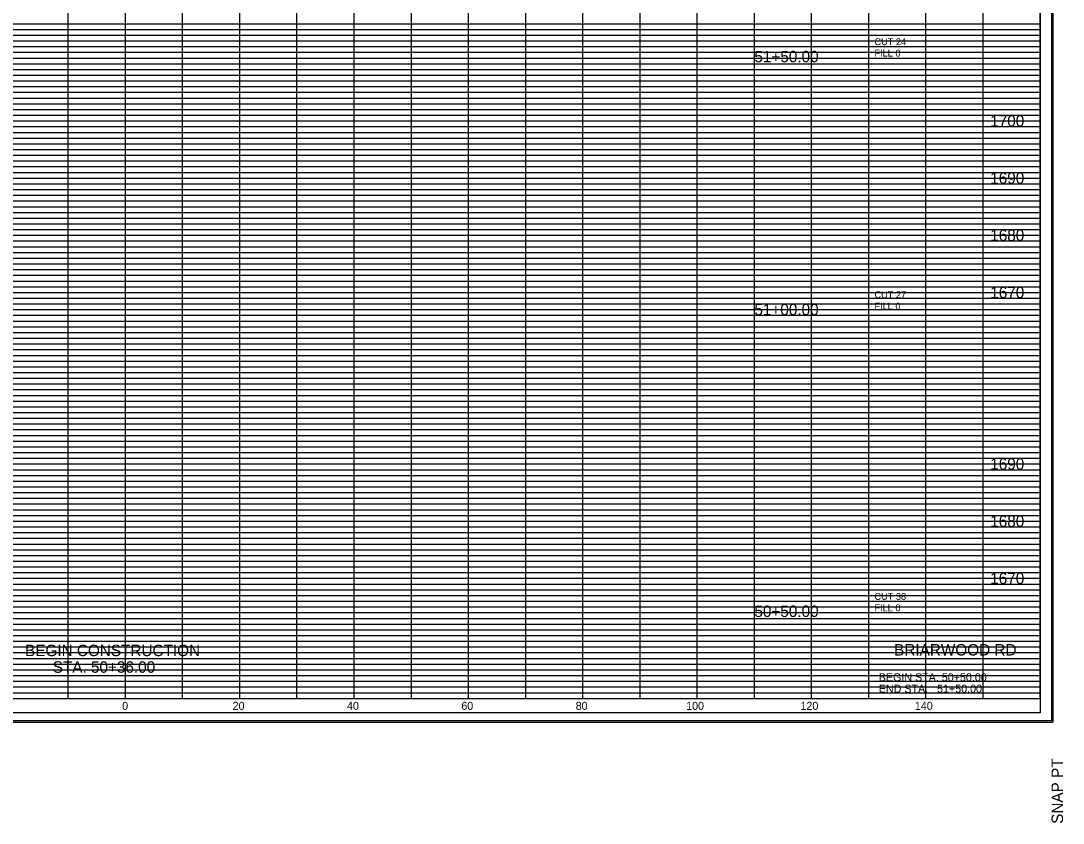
# Model space of a CAD drawing. Extents: x 980 to 2228, y 978 to 2394.
# Drawn here: x 1141.7 to 1324, y 978.2 to 1118.5 of the extents above; entities that cross this region are included whole.
import ezdxf

# ---------------------------------------------------------------- set-up
doc = ezdxf.new("R2010")
doc.units = 0
for name, color, linetype in [('DESIGN - SHEET - Corner Text', 7, 'Continuous'), ('DESIGN - SHEET - Light Grid', 7, 'Continuous'), ('DESIGN - SHEET - Linework', 7, 'Continuous'), ('DESIGN - SHEET - Plot Shape', 7, 'Continuous'), ('DESIGN - TYPICAL - Finished Grade and Subgrade', 7, 'Continuous'), ('DESIGN - TYPICAL - Text', 7, 'Continuous')]:
    doc.layers.add(name, color=color, linetype=linetype)

# ---------------------------------------------------------------- blocks, each defined once
blk = doc.blocks.new('XSTSHT')
at = {"layer": 'DESIGN - SHEET - Light Grid'}
for p, q in [((8, 11.8), (16, 11.8)), ((8, 11.7), (16, 11.7)), ((16, 11.8), (24, 11.8)), ((16, 11.7), (24, 11.7)), ((24, 11.8), (32, 11.8)), ((24, 11.7), (32, 11.7)), ((8, 11.6), (16, 11.6)), ((8, 11.5), (16, 11.5)), ((16, 11.6), (24, 11.6)), ((16, 11.5), (24, 11.5)), ((24, 11.6), (32, 11.6)), ((24, 11.5), (32, 11.5)), ((8, 11.4), (16, 11.4)), ((16, 11.4), (24, 11.4)), ((24, 11.4), (32, 11.4)), ((8, 11.3), (16, 11.3)), ((8, 11.2), (16, 11.2)), ((16, 11.3), (24, 11.3)), ((16, 11.2), (24, 11.2)), ((24, 11.3), (32, 11.3)), ((24, 11.2), (32, 11.2)), ((8, 11.1), (16, 11.1)), ((16, 11.1), (24, 11.1)), ((24, 11.1), (32, 11.1)), ((8, 10.9), (16, 10.9)), ((8, 10.8), (16, 10.8)), ((16, 10.9), (24, 10.9)), ((16, 10.8), (24, 10.8)), ((24, 10.9), (32, 10.9)), ((24, 10.8), (32, 10.8)), ((8, 10.7), (16, 10.7)), ((8, 10.6), (16, 10.6)), ((16, 10.7), (24, 10.7)), ((16, 10.6), (24, 10.6)), ((24, 10.7), (32, 10.7)), ((24, 10.6), (32, 10.6)), ((8, 10.5), (16, 10.5)), ((8, 10.4), (16, 10.4)), ((16, 10.5), (24, 10.5)), ((16, 10.4), (24, 10.4)), ((24, 10.5), (32, 10.5)), ((24, 10.4), (32, 10.4)), ((8, 10.3), (16, 10.3)), ((16, 10.3), (24, 10.3)), ((24, 10.3), (32, 10.3)), ((8, 10.2), (16, 10.2)), ((8, 10.1), (16, 10.1)), ((16, 10.2), (24, 10.2)), ((16, 10.1), (24, 10.1)), ((24, 10.2), (32, 10.2)), ((24, 10.1), (32, 10.1)), ((8, 9.9), (16, 9.9)), ((16, 9.9), (24, 9.9)), ((24, 9.9), (32, 9.9)), ((8, 9.8), (16, 9.8)), ((8, 9.7), (16, 9.7)), ((16, 9.8), (24, 9.8)), ((16, 9.7), (24, 9.7)), ((24, 9.8), (32, 9.8)), ((24, 9.7), (32, 9.7)), ((8, 9.6), (16, 9.6)), ((8, 9.5), (16, 9.5)), ((16, 9.6), (24, 9.6)), ((16, 9.5), (24, 9.5)), ((24, 9.6), (32, 9.6)), ((24, 9.5), (32, 9.5)), ((8, 9.4), (16, 9.4)), ((8, 9.3), (16, 9.3)), ((16, 9.4), (24, 9.4)), ((16, 9.3), (24, 9.3)), ((24, 9.4), (32, 9.4)), ((24, 9.3), (32, 9.3)), ((8, 9.2), (16, 9.2)), ((16, 9.2), (24, 9.2)), ((24, 9.2), (32, 9.2)), ((8, 9.1), (16, 9.1)), ((16, 9.1), (24, 9.1)), ((24, 9.1), (32, 9.1)), ((8, 8.9), (16, 8.9)), ((8, 8.8), (16, 8.8)), ((16, 8.9), (24, 8.9)), ((16, 8.8), (24, 8.8)), ((24, 8.9), (32, 8.9)), ((24, 8.8), (32, 8.8)), ((8, 8.7), (16, 8.7)), ((8, 8.6), (16, 8.6)), ((16, 8.7), (24, 8.7)), ((16, 8.6), (24, 8.6)), ((24, 8.7), (32, 8.7)), ((24, 8.6), (32, 8.6)), ((8, 8.5), (16, 8.5)), ((8, 8.4), (16, 8.4)), ((16, 8.5), (24, 8.5)), ((16, 8.4), (24, 8.4)), ((24, 8.5), (32, 8.5)), ((24, 8.4), (32, 8.4)), ((8, 8.3), (16, 8.3)), ((16, 8.3), (24, 8.3)), ((24, 8.3), (32, 8.3)), ((8, 8.2), (16, 8.2)), ((8, 8.1), (16, 8.1)), ((16, 8.2), (24, 8.2)), ((16, 8.1), (24, 8.1)), ((24, 8.2), (32, 8.2)), ((24, 8.1), (32, 8.1)), ((8, 7.9), (16, 7.9)), ((16, 7.9), (24, 7.9)), ((24, 7.9), (32, 7.9)), ((8, 7.8), (16, 7.8)), ((8, 7.7), (16, 7.7)), ((16, 7.8), (24, 7.8)), ((16, 7.7), (24, 7.7)), ((24, 7.8), (32, 7.8)), ((24, 7.7), (32, 7.7)), ((8, 7.6), (16, 7.6)), ((8, 7.5), (16, 7.5)), ((16, 7.6), (24, 7.6)), ((16, 7.5), (24, 7.5)), ((24, 7.6), (32, 7.6)), ((24, 7.5), (32, 7.5)), ((8, 7.4), (16, 7.4)), ((8, 7.3), (16, 7.3)), ((16, 7.4), (24, 7.4)), ((16, 7.3), (24, 7.3)), ((24, 7.4), (32, 7.4)), ((24, 7.3), (32, 7.3)), ((8, 7.2), (16, 7.2)), ((16, 7.2), (24, 7.2)), ((24, 7.2), (32, 7.2)), ((8, 7.1), (16, 7.1)), ((16, 7.1), (24, 7.1)), ((24, 7.1), (32, 7.1)), ((8, 6.9), (16, 6.9)), ((8, 6.8), (16, 6.8)), ((16, 6.9), (24, 6.9)), ((16, 6.8), (24, 6.8)), ((24, 6.9), (32, 6.9)), ((24, 6.8), (32, 6.8)), ((8, 6.7), (16, 6.7)), ((8, 6.6), (16, 6.6)), ((16, 6.7), (24, 6.7)), ((16, 6.6), (24, 6.6)), ((24, 6.7), (32, 6.7)), ((24, 6.6), (32, 6.6)), ((8, 6.5), (16, 6.5)), ((8, 6.4), (16, 6.4)), ((16, 6.5), (24, 6.5)), ((16, 6.4), (24, 6.4)), ((24, 6.5), (32, 6.5)), ((24, 6.4), (32, 6.4)), ((8, 6.3), (16, 6.3)), ((8, 6.2), (16, 6.2)), ((16, 6.3), (24, 6.3)), ((16, 6.2), (24, 6.2)), ((24, 6.3), (32, 6.3)), ((24, 6.2), (32, 6.2)), ((8, 6.1), (16, 6.1)), ((16, 6.1), (24, 6.1)), ((24, 6.1), (32, 6.1)), ((8, 5.9), (16, 5.9)), ((16, 5.9), (24, 5.9)), ((24, 5.9), (32, 5.9)), ((8, 5.8), (16, 5.8)), ((8, 5.7), (16, 5.7)), ((16, 5.8), (24, 5.8)), ((16, 5.7), (24, 5.7)), ((24, 5.8), (32, 5.8)), ((24, 5.7), (32, 5.7)), ((8, 5.6), (16, 5.6)), ((8, 5.5), (16, 5.5)), ((16, 5.6), (24, 5.6)), ((16, 5.5), (24, 5.5)), ((24, 5.6), (32, 5.6)), ((24, 5.5), (32, 5.5)), ((8, 5.4), (16, 5.4)), ((8, 5.3), (16, 5.3)), ((16, 5.4), (24, 5.4)), ((16, 5.3), (24, 5.3)), ((24, 5.4), (32, 5.4)), ((24, 5.3), (32, 5.3)), ((8, 5.2), (16, 5.2)), ((16, 5.2), (24, 5.2)), ((24, 5.2), (32, 5.2)), ((8, 5.1), (16, 5.1)), ((16, 5.1), (24, 5.1)), ((24, 5.1), (32, 5.1)), ((8, 4.9), (16, 4.9)), ((8, 4.8), (16, 4.8)), ((16, 4.9), (24, 4.9)), ((16, 4.8), (24, 4.8)), ((24, 4.9), (32, 4.9)), ((24, 4.8), (32, 4.8)), ((8, 4.7), (16, 4.7)), ((8, 4.6), (16, 4.6)), ((16, 4.7), (24, 4.7)), ((16, 4.6), (24, 4.6)), ((24, 4.7), (32, 4.7)), ((24, 4.6), (32, 4.6)), ((8, 4.5), (16, 4.5)), ((8, 4.4), (16, 4.4)), ((16, 4.5), (24, 4.5)), ((16, 4.4), (24, 4.4)), ((24, 4.5), (32, 4.5)), ((24, 4.4), (32, 4.4)), ((8, 4.3), (16, 4.3)), ((8, 4.2), (16, 4.2)), ((16, 4.3), (24, 4.3)), ((16, 4.2), (24, 4.2)), ((24, 4.3), (32, 4.3)), ((24, 4.2), (32, 4.2)), ((8, 4.1), (16, 4.1)), ((16, 4.1), (24, 4.1)), ((24, 4.1), (32, 4.1)), ((8, 3.9), (16, 3.9)), ((16, 3.9), (24, 3.9)), ((24, 3.9), (32, 3.9)), ((8, 3.8), (16, 3.8)), ((8, 3.7), (16, 3.7)), ((16, 3.8), (24, 3.8)), ((16, 3.7), (24, 3.7)), ((24, 3.8), (32, 3.8)), ((24, 3.7), (32, 3.7)), ((8, 3.6), (16, 3.6)), ((8, 3.5), (16, 3.5)), ((16, 3.6), (24, 3.6)), ((16, 3.5), (24, 3.5)), ((24, 3.6), (32, 3.6)), ((24, 3.5), (32, 3.5)), ((8, 3.4), (16, 3.4)), ((8, 3.3), (16, 3.3)), ((16, 3.4), (24, 3.4)), ((16, 3.3), (24, 3.3)), ((24, 3.4), (32, 3.4)), ((24, 3.3), (32, 3.3)), ((8, 3.2), (16, 3.2)), ((8, 3.1), (16, 3.1)), ((16, 3.2), (24, 3.2)), ((16, 3.1), (24, 3.1)), ((24, 3.2), (32, 3.2)), ((24, 3.1), (32, 3.1)), ((8, 2.9), (16, 2.9)), ((8, 2.8), (16, 2.8)), ((16, 2.9), (24, 2.9)), ((16, 2.8), (24, 2.8)), ((24, 2.9), (32, 2.9)), ((24, 2.8), (32, 2.8)), ((8, 2.7), (16, 2.7)), ((8, 2.6), (16, 2.6)), ((16, 2.7), (24, 2.7)), ((16, 2.6), (24, 2.6)), ((24, 2.7), (32, 2.7)), ((24, 2.6), (32, 2.6)), ((8, 2.5), (16, 2.5)), ((8, 2.4), (16, 2.4)), ((16, 2.5), (24, 2.5)), ((16, 2.4), (24, 2.4)), ((24, 2.5), (32, 2.5)), ((24, 2.4), (32, 2.4)), ((8, 2.3), (16, 2.3)), ((8, 2.2), (16, 2.2)), ((16, 2.3), (24, 2.3)), ((16, 2.2), (24, 2.2)), ((24, 2.3), (32, 2.3)), ((24, 2.2), (32, 2.2)), ((8, 2.1), (16, 2.1)), ((16, 2.1), (24, 2.1)), ((24, 2.1), (32, 2.1)), ((8, 1.9), (16, 1.9)), ((16, 1.9), (24, 1.9)), ((24, 1.9), (32, 1.9)), ((8, 1.8), (16, 1.8)), ((8, 1.7), (16, 1.7)), ((16, 1.8), (24, 1.8)), ((16, 1.7), (24, 1.7)), ((24, 1.8), (32, 1.8)), ((24, 1.7), (32, 1.7)), ((8, 1.6), (16, 1.6)), ((8, 1.5), (16, 1.5)), ((16, 1.6), (24, 1.6)), ((16, 1.5), (24, 1.5)), ((24, 1.6), (32, 1.6)), ((24, 1.5), (32, 1.5)), ((8, 1.4), (16, 1.4)), ((8, 1.3), (16, 1.3)), ((16, 1.4), (24, 1.4)), ((16, 1.3), (24, 1.3)), ((24, 1.4), (32, 1.4)), ((24, 1.3), (32, 1.3)), ((8, 1.2), (16, 1.2)), ((8, 1.1), (16, 1.1)), ((16, 1.2), (24, 1.2)), ((16, 1.1), (24, 1.1)), ((24, 1.2), (32, 1.2)), ((24, 1.1), (32, 1.1)), ((8, 0.9), (16, 0.9)), ((8, 0.8), (16, 0.8)), ((16, 0.9), (24, 0.9)), ((16, 0.8), (24, 0.8)), ((24, 0.9), (32, 0.9)), ((24, 0.8), (32, 0.8)), ((8, 0.7), (16, 0.7)), ((8, 0.6), (16, 0.6)), ((16, 0.7), (24, 0.7)), ((16, 0.6), (24, 0.6)), ((24, 0.7), (32, 0.7)), ((24, 0.6), (32, 0.6)), ((8, 0.5), (16, 0.5)), ((8, 0.4), (16, 0.4)), ((16, 0.5), (24, 0.5)), ((16, 0.4), (24, 0.4)), ((24, 0.5), (32, 0.5)), ((24, 0.4), (32, 0.4)), ((8, 0.3), (16, 0.3)), ((8, 0.2), (16, 0.2)), ((16, 0.3), (24, 0.3)), ((16, 0.2), (24, 0.2)), ((24, 0.3), (32, 0.3)), ((24, 0.2), (32, 0.2)), ((8, 0.1), (16, 0.1)), ((16, 0.1), (24, 0.1)), ((24, 0.1), (32, 0.1))]:
    blk.add_line(p, q, dxfattribs=at)
at = {"layer": 'DESIGN - SHEET - Linework'}
for p, q in [((32.217, 21.414), (32.217, -0.414)), ((15, 0), (15, 21)), ((16, 0), (16, 21)), ((17, 0), (17, 21)), ((18, 0), (18, 21)), ((19, 0), (19, 21)), ((20, 0), (20, 21)), ((21, 0), (21, 21)), ((22, 0), (22, 21)), ((23, 0), (23, 21)), ((24, 0), (24, 21)), ((25, 0), (25, 21)), ((26, 0), (26, 21)), ((27, 0), (27, 21)), ((28, 0), (28, 20)), ((29, 0), (29, 20)), ((30, 0), (30, 20)), ((31, 0), (31, 20)), ((0, 11), (32, 11)), ((0, 10), (32, 10)), ((0, 9), (32, 9)), ((0, 8), (32, 8)), ((0, 7), (32, 7)), ((0, 6), (32, 6)), ((0, 5), (32, 5)), ((0, 4), (32, 4)), ((0, 3), (32, 3)), ((0, 2), (32, 2)), ((0, 1), (32, 1)), ((-1.823, -0.414), (32.217, -0.414))]:
    blk.add_line(p, q, dxfattribs=at)
blk.add_lwpolyline([(0, 21), (0, 0), (32, 0), (32, 21), (0, 21)], dxfattribs=at)
at = {"layer": 'DESIGN - SHEET - Plot Shape'}
for points in [[(-1.803, 21.394), (32.197, 21.394), (32.197, -0.394), (-1.803, -0.394)], [(-0.85, 21), (32, 21), (32, -0.25), (-0.85, -0.25)]]:
    blk.add_lwpolyline(points, close=True, dxfattribs=at)
at = {"layer": 'DESIGN - SHEET - Corner Text'}
blk.add_text('SNAP PT  ', height=0.2, rotation=90, dxfattribs=at).set_placement((32.397, -2.194))

msp = doc.modelspace()

# ---------------------------------------------------------------- linework, layer by layer
at = {"layer": 'DESIGN - SHEET - Plot Shape'}
msp.add_lwpolyline([(991.5, 1210), (1320, 1210), (1320, 997.5), (991.5, 997.5)], close=True, dxfattribs=at)

# ---------------------------------------------------------------- block references
at = {"layer": 'DESIGN - TYPICAL - Finished Grade and Subgrade', "xscale": 10, "yscale": 10}
msp.add_blockref('XSTSHT', (1000, 1000), dxfattribs=at)

# ---------------------------------------------------------------- texts
at = {"layer": 'DESIGN - SHEET - Corner Text'}
for s, height, p in [('1700', 2, (1311.25, 1100)), ('1690', 2, (1311.25, 1090)), ('1680', 2, (1311.25, 1080)), ('1670', 2, (1311.25, 1070)), ('1690', 2, (1311.25, 1040)), ('1680', 2, (1311.25, 1030)), ('1670', 2, (1311.25, 1020)), ('BRIARWOOD RD', 2, (1294.44, 1007.5)), ('BEGIN STA. 50+50.00', 1.4, (1291.75, 1003)), ('END STA.   51+50.00', 1.4, (1291.75, 1001)), ('0', 1.4, (1159.42, 998)), ('0', 1.4, (1159.42, 998)), ('20', 1.4, (1178.74, 998)), ('40', 1.4, (1198.74, 998)), ('60', 1.4, (1218.74, 998)), ('80', 1.4, (1238.74, 998)), ('100', 1.4, (1258.06, 998)), ('120', 1.4, (1278.06, 998)), ('140', 1.4, (1298.06, 998))]:
    msp.add_text(s, height=height, dxfattribs=at).set_placement(p)
at = {"layer": 'DESIGN - TYPICAL - Text'}
for s, height, p in [('CUT 24', 1.2, (1291, 1114.25)), ('51+50.00', 2, (1270, 1111.25)), ('FILL 0', 1.2, (1291, 1112.25)), ('CUT 27', 1.2, (1291, 1070.01)), ('51+00.00', 2, (1270, 1067.01)), ('FILL 0', 1.2, (1291, 1068.01)), ('CUT 38', 1.2, (1291, 1017.24)), ('50+50.00', 2, (1270, 1014.24)), ('FILL 0', 1.2, (1291, 1015.24)), ('BEGIN CONSTRUCTION', 2, (1142.44, 1007.39)), ('STA. 50+36.00', 2, (1147.28, 1004.49))]:
    msp.add_text(s, height=height, dxfattribs=at).set_placement(p)

doc.saveas('drawing.dxf')
